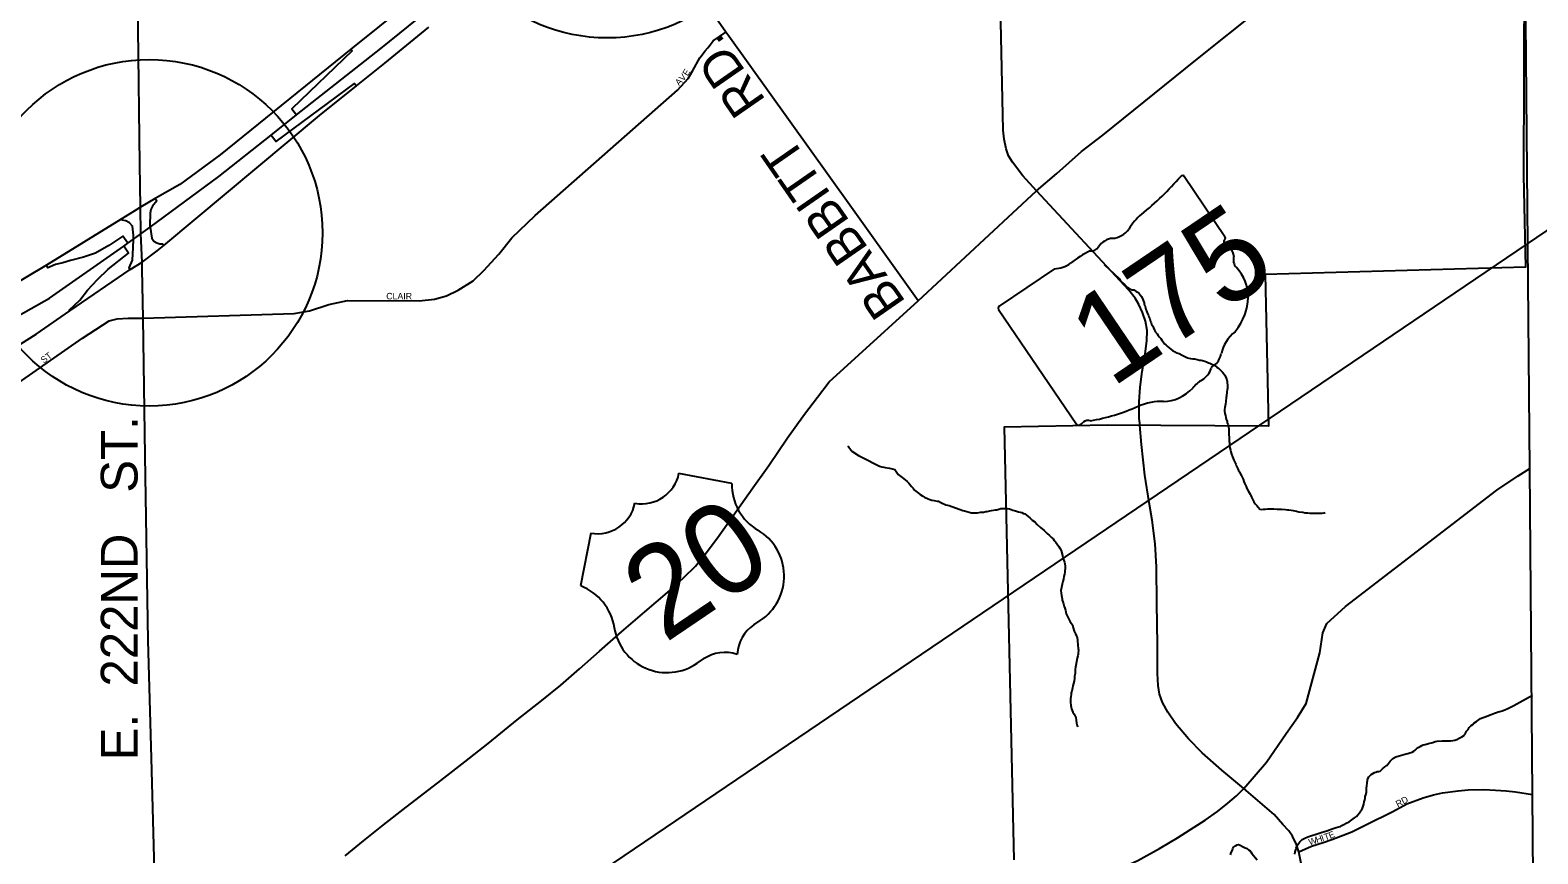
# Model space of a CAD drawing. Extents: x 2139079 to 2262683, y 1235796 to 1334992.
# Drawn here: x 2234072 to 2245568, y 1303635 to 1309915 of the extents above; entities that cross this region are included whole.
import ezdxf

# ---------------------------------------------------------------- set-up
doc = ezdxf.new("R2010")
doc.units = 0
for name, color, linetype in [('GM_X_Adjacent_County', 7, 'Continuous'), ('GM_X_City_Street', 7, 'Continuous'), ('GM_X_City_Street_Text', 7, 'Continuous'), ('GM_X_Interchange_Ramps', 7, 'Continuous'), ('GM_X_Interstate_Route', 7, 'Continuous'), ('GM_X_Minor_River', 7, 'Continuous'), ('GM_X_State_Location', 7, 'Continuous'), ('GM_X_State_Route', 7, 'Continuous'), ('GM_X_State_Shield', 7, 'Continuous'), ('GM_X_US_Location', 7, 'Continuous'), ('GM_X_US_Route', 7, 'Continuous'), ('GM_X_US_Shield', 7, 'Continuous'), ('SH_Text', 7, 'Continuous')]:
    doc.layers.add(name, color=color, linetype=linetype)

msp = doc.modelspace()

# ---------------------------------------------------------------- linework, layer by layer
at = {"layer": 'GM_X_Adjacent_County'}
msp.add_lwpolyline([(2245541, 1302192), (2245528, 1304087), (2245507, 1306573), (2245466, 1311124), (2245451, 1311744), (2245406, 1312275), (2245366, 1313013), (2245298, 1316197), (2245294, 1316360), (2245278, 1317130), (2245271, 1317437), (2245264, 1317789), (2245234, 1319644), (2245190, 1321250), (2245174, 1321990), (2245155, 1322872), (2245144, 1323376), (2245140, 1323785), (2245134, 1324581), (2245318, 1324775), (2245503, 1324980), (2245556, 1325020), (2245646, 1325055)], dxfattribs=at)
at = {"layer": 'GM_X_City_Street'}
for points in [[(2234909, 1308893), (2234870, 1311991), (2234797, 1316346), (2234781, 1316477)], [(2241391, 1313747), (2241308, 1313700), (2241239, 1313644), (2240849, 1313342), (2240048, 1312674), (2239503, 1312219), (2238476, 1311361), (2238395, 1311294), (2238315, 1311229), (2237753, 1310771), (2237032, 1310186), (2236735, 1309945), (2236518, 1309769), (2235520, 1308963), (2235213, 1308739), (2235026, 1308631), (2234914, 1308565), (2234865, 1308535)], [(2239398, 1309868), (2239376, 1309899), (2238560, 1311072), (2238478, 1311183), (2238395, 1311294)], [(2234926, 1308146), (2235041, 1308233), (2235092, 1308272), (2236278, 1309265), (2236560, 1309490), (2236776, 1309663), (2237111, 1309938)], [(2239257, 1309803), (2239281, 1309833), (2239376, 1309899)], [(2240321, 1308580), (2239398, 1309868)], [(2234934, 1307718), (2236085, 1307754), (2236202, 1307776), (2236350, 1307823), (2236491, 1307854), (2237039, 1307852), (2237154, 1307863), (2237247, 1307889), (2237336, 1307932), (2237449, 1308004), (2237530, 1308082), (2237645, 1308208), (2237745, 1308332), (2237923, 1308502), (2239008, 1309457), (2239090, 1309546), (2239124, 1309607), (2239179, 1309703), (2239220, 1309758), (2239239, 1309781), (2239257, 1309803)], [(2234927, 1308092), (2234926, 1308146), (2234917, 1308361), (2234914, 1308565), (2234909, 1308893)], [(2240844, 1307851), (2240321, 1308580)], [(2234865, 1308535), (2234767, 1308474), (2234196, 1308122), (2232556, 1307145), (2232165, 1306913), (2231754, 1306642), (2231295, 1306315)], [(2231412, 1306001), (2232025, 1306429), (2232297, 1306605), (2232573, 1306755), (2232743, 1306842), (2233049, 1306993), (2233510, 1307216), (2234119, 1307596), (2234374, 1307775), (2234835, 1308090), (2234926, 1308146)], [(2234934, 1307718), (2234927, 1308092)], [(2231078, 1305046), (2231495, 1305379), (2231714, 1305558), (2232083, 1305854), (2232970, 1306469), (2233503, 1306893), (2233761, 1307074), (2234472, 1307567), (2234675, 1307698), (2234735, 1307713), (2234819, 1307719), (2234934, 1307718)], [(2234950, 1306670), (2234934, 1307718)], [(2234997, 1304365), (2234973, 1305262), (2234950, 1306670)], [(2235037, 1302845), (2234997, 1304365)], [(2243746, 1303651), (2243841, 1303694), (2243931, 1303722), (2243998, 1303744), (2244149, 1303802), (2244261, 1303858), (2244463, 1303958), (2244569, 1304016), (2244693, 1304062), (2244773, 1304086), (2244841, 1304100), (2244961, 1304116), (2245037, 1304124), (2245157, 1304125), (2245245, 1304121), (2245325, 1304115), (2245398, 1304107), (2245528, 1304087)]]:
    msp.add_lwpolyline(points, dxfattribs=at)
at = {"layer": 'GM_X_Interchange_Ramps'}
for points in [[(2236518, 1309769), (2236528, 1309757), (2236067, 1309315), (2236104, 1309268)], [(2235909, 1309114), (2235947, 1309067), (2236545, 1309508), (2236560, 1309490)], [(2235026, 1308631), (2235037, 1308613), (2235004, 1308573), (2234993, 1308547), (2234987, 1308519), (2234985, 1308426), (2234987, 1308413), (2235000, 1308329), (2235016, 1308307), (2235039, 1308294), (2235061, 1308286), (2235082, 1308285), (2235092, 1308272)], [(2234835, 1308090), (2234827, 1308103), (2234853, 1308162), (2234858, 1308257), (2234860, 1308321), (2234860, 1308352), (2234852, 1308420), (2234829, 1308447), (2234801, 1308461), (2234774, 1308465), (2234767, 1308474)], [(2234817, 1308291), (2234779, 1308345), (2234672, 1308272), (2234571, 1308215), (2234480, 1308184), (2234379, 1308159), (2234320, 1308142), (2234264, 1308127), (2234208, 1308103), (2234196, 1308122)], [(2234374, 1307775), (2234370, 1307780), (2234450, 1307856), (2234508, 1307932), (2234585, 1308015), (2234667, 1308092), (2234823, 1308215), (2234786, 1308269)]]:
    msp.add_lwpolyline(points, dxfattribs=at)
at = {"layer": 'GM_X_Interstate_Route'}
for points in [[(2245142, 1323484), (2245178, 1321773), (2245406, 1312275), (2245451, 1311744), (2245466, 1311124), (2245458, 1308807), (2245473, 1308109), (2243489, 1308053), (2243515, 1306895), (2242283, 1306903), (2241498, 1306888), (2241571, 1303589)], [(2245142, 1323484), (2245178, 1321773), (2245406, 1312275), (2245451, 1311744), (2245466, 1311124), (2245458, 1308807), (2245473, 1308109), (2243489, 1308053), (2243515, 1306895), (2242283, 1306903), (2241498, 1306888), (2241571, 1303589)], [(2232924, 1307142), (2234220, 1307872), (2234786, 1308269), (2234817, 1308291), (2234860, 1308321), (2234917, 1308361), (2234987, 1308413), (2235511, 1308800), (2235909, 1309114), (2236104, 1309268), (2236747, 1309775), (2237510, 1310396), (2237574, 1310448), (2238417, 1311133), (2238478, 1311183), (2238522, 1311219), (2239158, 1311738), (2239253, 1311815), (2240623, 1312932), (2240702, 1312997), (2241356, 1313531), (2241390, 1313558)]]:
    msp.add_lwpolyline(points, dxfattribs=at)
at = {"layer": 'GM_X_Minor_River'}
for points in [[(2242261, 1308127), (2242378, 1308019), (2242389, 1307999), (2242403, 1307987), (2242413, 1307980), (2242425, 1307966), (2242439, 1307954), (2242451, 1307946), (2242461, 1307940), (2242475, 1307936), (2242488, 1307934), (2242504, 1307922), (2242516, 1307917), (2242528, 1307907), (2242536, 1307897), (2242546, 1307883), (2242556, 1307861), (2242561, 1307849), (2242565, 1307837), (2242567, 1307827), (2242571, 1307817), (2242573, 1307807), (2242575, 1307797), (2242579, 1307785), (2242583, 1307775), (2242588, 1307759), (2242594, 1307749), (2242598, 1307739), (2242602, 1307729), (2242608, 1307713), (2242612, 1307703), (2242614, 1307693), (2242619, 1307683), (2242623, 1307673), (2242631, 1307657), (2242637, 1307645), (2242645, 1307627), (2242653, 1307613), (2242664, 1307599), (2242672, 1307587), (2242680, 1307577), (2242692, 1307563), (2242700, 1307552), (2242710, 1307538), (2242721, 1307524), (2242731, 1307516), (2242741, 1307506), (2242759, 1307490), (2242769, 1307482), (2242785, 1307470), (2242797, 1307466), (2242815, 1307456), (2242832, 1307449), (2242856, 1307437), (2242872, 1307429), (2242882, 1307423), (2242896, 1307417), (2242906, 1307415), (2242918, 1307411), (2242936, 1307408), (2242950, 1307408), (2242970, 1307404), (2242988, 1307400), (2242998, 1307398), (2243012, 1307396), (2243029, 1307391), (2243041, 1307387), (2243057, 1307379), (2243067, 1307377), (2243087, 1307367), (2243103, 1307361), (2243123, 1307342), (2243133, 1307338), (2243150, 1307320), (2243162, 1307308), (2243174, 1307294), (2243180, 1307284), (2243192, 1307262), (2243196, 1307248), (2243199, 1307236), (2243199, 1307224), (2243201, 1307214), (2243201, 1307184), (2243199, 1307174), (2243196, 1307156), (2243194, 1307126), (2243192, 1307114), (2243188, 1307083), (2243185, 1307063), (2243181, 1307039), (2243179, 1307023), (2243179, 1307009), (2243181, 1306993), (2243185, 1306977), (2243188, 1306961), (2243192, 1306949)], [(2243192, 1306949), (2243198, 1306931), (2243200, 1306921), (2243206, 1306907), (2243210, 1306895), (2243211, 1306867), (2243211, 1306843), (2243211, 1306829), (2243213, 1306811), (2243214, 1306781), (2243216, 1306769), (2243216, 1306751), (2243220, 1306731), (2243225, 1306713), (2243227, 1306699), (2243233, 1306681), (2243239, 1306663), (2243245, 1306649), (2243249, 1306637), (2243254, 1306627), (2243260, 1306615), (2243264, 1306605), (2243268, 1306595), (2243274, 1306581), (2243280, 1306571), (2243286, 1306559), (2243292, 1306547), (2243299, 1306535), (2243309, 1306517), (2243321, 1306491), (2243327, 1306475), (2243332, 1306461), (2243338, 1306447), (2243344, 1306435), (2243350, 1306421), (2243360, 1306403), (2243366, 1306389), (2243373, 1306377), (2243379, 1306366), (2243385, 1306354), (2243391, 1306340), (2243397, 1306330), (2243403, 1306320), (2243413, 1306304), (2243424, 1306290), (2243434, 1306278), (2243448, 1306262), (2243460, 1306260), (2243476, 1306262), (2243492, 1306262), (2243510, 1306265), (2243530, 1306265), (2243544, 1306265), (2243554, 1306265), (2243580, 1306263), (2243592, 1306264), (2243612, 1306262), (2243644, 1306260), (2243658, 1306258), (2243670, 1306258), (2243686, 1306255), (2243701, 1306253), (2243715, 1306249), (2243727, 1306247), (2243745, 1306243), (2243775, 1306239), (2243793, 1306236), (2243805, 1306236), (2243815, 1306234), (2243829, 1306232), (2243839, 1306232), (2243851, 1306232), (2243863, 1306232), (2243875, 1306232), (2243887, 1306233), (2243899, 1306233), (2243911, 1306233), (2243923, 1306233), (2243939, 1306235), (2243945, 1306237)], [(2240305, 1306744), (2240313, 1306736), (2240338, 1306704), (2240389, 1306671), (2240444, 1306644), (2240517, 1306607), (2240533, 1306599), (2240549, 1306592), (2240566, 1306586), (2240580, 1306584), (2240590, 1306580), (2240624, 1306575), (2240654, 1306568), (2240666, 1306566), (2240691, 1306528), (2240732, 1306497), (2240759, 1306475), (2240771, 1306461), (2240781, 1306449), (2240792, 1306436), (2240804, 1306422), (2240814, 1306408), (2240824, 1306400), (2240835, 1306392), (2240845, 1306384), (2240857, 1306375), (2240879, 1306363), (2240894, 1306353), (2240908, 1306347), (2240920, 1306342), (2240932, 1306336), (2240948, 1306332), (2240966, 1306329), (2240987, 1306325), (2240997, 1306325), (2241021, 1306312), (2241053, 1306296), (2241080, 1306291), (2241183, 1306252), (2241197, 1306249), (2241213, 1306245), (2241231, 1306239), (2241249, 1306236), (2241272, 1306234), (2241294, 1306234), (2241318, 1306239), (2241342, 1306241), (2241358, 1306244), (2241370, 1306246), (2241388, 1306250), (2241402, 1306253), (2241418, 1306255), (2241432, 1306259), (2241442, 1306259), (2241472, 1306268), (2241502, 1306269), (2241524, 1306267), (2241538, 1306265), (2241564, 1306256), (2241584, 1306250), (2241609, 1306243), (2241633, 1306237), (2241645, 1306231), (2241655, 1306227), (2241680, 1306210), (2241696, 1306194), (2241712, 1306178), (2241733, 1306167), (2241751, 1306147), (2241776, 1306123), (2241804, 1306100), (2241827, 1306078), (2241843, 1306062), (2241860, 1306048), (2241872, 1306037), (2241880, 1306025), (2241891, 1306013), (2241903, 1305997), (2241915, 1305979), (2241924, 1305965), (2241932, 1305949), (2241945, 1305899), (2241952, 1305878), (2241958, 1305860), (2241960, 1305846), (2241963, 1305828), (2241963, 1305815), (2241963, 1305805), (2241961, 1305795), (2241960, 1305783), (2241958, 1305767), (2241954, 1305749), (2241951, 1305729), (2241947, 1305711), (2241941, 1305690), (2241936, 1305666), (2241930, 1305644), (2241933, 1305622), (2241935, 1305606), (2241937, 1305592), (2241940, 1305580)], [(2241940, 1305580), (2241942, 1305570), (2241946, 1305556), (2241950, 1305542), (2241953, 1305530), (2241957, 1305520), (2241961, 1305508), (2241965, 1305492), (2241970, 1305464), (2241983, 1305440), (2241993, 1305420), (2242001, 1305404), (2242012, 1305392), (2242020, 1305381), (2242024, 1305359), (2242033, 1305333), (2242043, 1305313), (2242050, 1305295), (2242054, 1305285), (2242057, 1305261), (2242059, 1305227), (2242064, 1305201), (2242066, 1305189), (2242064, 1305168), (2242063, 1305158), (2242061, 1305144), (2242055, 1305128), (2242044, 1305072), (2242043, 1305058), (2242041, 1305043), (2242041, 1305029), (2242040, 1305009), (2242036, 1304991), (2242034, 1304975), (2242031, 1304953), (2242027, 1304933), (2242023, 1304917), (2242020, 1304900), (2242018, 1304888), (2242014, 1304876), (2242010, 1304862), (2242009, 1304850), (2242007, 1304834), (2242005, 1304816), (2242004, 1304792), (2242008, 1304766), (2242013, 1304740), (2242021, 1304716), (2242032, 1304700), (2242038, 1304690), (2242044, 1304674), (2242047, 1304654), (2242051, 1304632), (2242056, 1304612), (2242060, 1304608), (2242060, 1304606)], [(2244366, 1304266), (2244382, 1304284), (2244400, 1304299), (2244416, 1304309), (2244427, 1304321), (2244433, 1304331), (2244441, 1304343), (2244461, 1304363), (2244485, 1304374), (2244509, 1304382), (2244529, 1304388), (2244547, 1304392), (2244563, 1304397), (2244577, 1304401), (2244591, 1304405), (2244609, 1304411), (2244621, 1304417), (2244631, 1304425), (2244643, 1304436), (2244656, 1304446), (2244670, 1304454), (2244684, 1304462), (2244694, 1304466), (2244708, 1304470), (2244734, 1304477), (2244766, 1304485), (2244786, 1304491), (2244800, 1304495), (2244838, 1304498), (2244870, 1304496), (2244902, 1304497), (2244920, 1304499), (2244934, 1304501), (2244950, 1304507), (2244968, 1304517), (2244988, 1304528), (2245002, 1304536), (2245016, 1304556), (2245024, 1304570), (2245036, 1304584), (2245045, 1304598), (2245059, 1304613), (2245071, 1304621), (2245079, 1304631), (2245101, 1304645), (2245131, 1304668), (2245179, 1304684), (2245211, 1304698), (2245237, 1304707), (2245253, 1304713), (2245264, 1304717), (2245278, 1304721), (2245296, 1304726), (2245316, 1304734), (2245338, 1304744), (2245364, 1304756), (2245384, 1304767), (2245527, 1304844)], [(2243714, 1303633), (2243718, 1303651), (2243722, 1303667), (2243725, 1303679), (2243733, 1303699), (2243745, 1303716), (2243753, 1303728), (2243771, 1303744), (2243791, 1303754), (2243815, 1303765), (2243837, 1303773), (2243853, 1303777), (2243871, 1303783), (2243922, 1303800), (2243942, 1303806), (2243960, 1303812), (2243978, 1303819), (2243992, 1303823), (2244008, 1303829), (2244030, 1303837), (2244050, 1303841), (2244062, 1303845), (2244072, 1303852), (2244088, 1303858), (2244106, 1303870), (2244130, 1303880), (2244150, 1303895), (2244170, 1303909), (2244184, 1303921), (2244195, 1303933), (2244207, 1303947), (2244217, 1303962), (2244225, 1303972), (2244231, 1303984), (2244237, 1303998), (2244241, 1304014), (2244244, 1304032), (2244248, 1304048), (2244250, 1304060), (2244252, 1304072), (2244256, 1304086), (2244260, 1304104), (2244261, 1304118), (2244261, 1304133), (2244265, 1304157), (2244267, 1304171), (2244267, 1304183), (2244272, 1304209), (2244280, 1304223), (2244296, 1304241), (2244310, 1304249), (2244322, 1304256), (2244332, 1304258), (2244342, 1304262), (2244356, 1304264), (2244366, 1304266)], [(2243225, 1303628), (2243229, 1303646), (2243239, 1303664), (2243243, 1303676), (2243248, 1303686), (2243262, 1303696), (2243274, 1303703), (2243286, 1303707), (2243298, 1303701), (2243317, 1303691), (2243337, 1303681), (2243351, 1303675), (2243361, 1303665), (2243373, 1303659), (2243379, 1303650), (2243387, 1303638), (2243428, 1303590)]]:
    msp.add_lwpolyline(points, dxfattribs=at)
at = {"layer": 'GM_X_State_Route'}
for points in [[(2241744, 1308690), (2241641, 1308805), (2241562, 1308908), (2241532, 1308957), (2241513, 1309011), (2241499, 1309083), (2241491, 1309152), (2241462, 1310453)], [(2242532, 1306918), (2242529, 1306955), (2242527, 1307082), (2242535, 1307192), (2242551, 1307312), (2242573, 1307447), (2242586, 1307546), (2242588, 1307625), (2242577, 1307696), (2242553, 1307761), (2242525, 1307824), (2242498, 1307872), (2242448, 1307933), (2241744, 1308690)], [(2243326, 1304133), (2243157, 1304273), (2243007, 1304405), (2242903, 1304511), (2242806, 1304628), (2242746, 1304715), (2242707, 1304788), (2242684, 1304852), (2242673, 1304918), (2242667, 1305010), (2242667, 1305232), (2242662, 1305543), (2242660, 1305823), (2242649, 1305998), (2242628, 1306180), (2242603, 1306313), (2242570, 1306521), (2242546, 1306755), (2242533, 1306903), (2242532, 1306918)], [(2243759, 1303247), (2243764, 1303275), (2243770, 1303379), (2243769, 1303477), (2243763, 1303561), (2243746, 1303651), (2243727, 1303707), (2243698, 1303769), (2243669, 1303810), (2243624, 1303860), (2243557, 1303935), (2243326, 1304133)]]:
    msp.add_lwpolyline(points, dxfattribs=at)
at = {"layer": 'GM_X_State_Shield'}
for p, q in [((2243182, 1308340), (2242872, 1308798)), ((2243182, 1308340), (2243182, 1308340)), ((2241882, 1308096), (2241460, 1307810)), ((2241456, 1307785), (2242049, 1306911))]:
    msp.add_line(p, q, dxfattribs=at)
for centre, major_axis, start_param, end_param in [((2241566, 1309621), (1528, 1035), 4.814394, 5.042369), ((2242855, 1308789), (16, 10.9), 6.141152, 7.989035), ((2242750, 1308294), (307, 208), 1.699011, 2.107814), ((2242311, 1308226), (97.1, 65.8), 0.950623, 2.079405), ((2242343, 1308450), (117, 79), 4.081561, 5.145723), ((2243166, 1308327), (17.2, 11.6), 5.05454, 6.418171), ((2242369, 1307709), (581, 394), 1.404758, 1.657858), ((2242174, 1308281), (46.7, 31.6), 3.836095, 5.185415), ((2243201, 1308304), (24.8, 16.8), 1.883978, 3.671073), ((2243083, 1308140), (149, 101), 5.934695, 6.695948), ((2241914, 1308266), (162, 110), 4.042523, 4.731795), ((2243369, 1308188), (108, 73), 2.387724, 3.262537), ((2242924, 1307801), (382, 259), 5.101752, 6.440018), ((2241472, 1307798), (16.7, 11.3), 1.712693, 3.28349), ((2243390, 1307460), (209, 142), 1.647645, 2.488434), ((2243015, 1307442), (123, 84), 4.937069, 5.64225), ((2242948, 1307344), (117, 79), 4.691044, 5.507374), ((2243111, 1307331), (32.9, 22.3), 1.147584, 2.315152), ((2242761, 1307313), (219, 148), 4.026481, 4.996735), ((2243092, 1307096), (180, 122), 1.495662, 1.94098), ((2242617, 1306722), (345, 234), 0.823519, 1.323587), ((2242129, 1306891), (46.3, 31.4), 0.519207, 1.627899), ((2242181, 1308073), (1103, 747), 4.195997, 4.488961), ((2242067, 1306920), (16.8, 11.4), 3.00124, 4.508301), ((2242009, 1307011), (129, 87), 4.665946, 4.897461)]:
    msp.add_ellipse(centre, major_axis=major_axis, ratio=0.8, start_param=start_param, end_param=end_param, dxfattribs=at)
at = {"layer": 'GM_X_US_Route'}
msp.add_lwpolyline([(2202868, 1295541), (2210354, 1284489), (2249318, 1310882), (2241832, 1321934)], close=True, dxfattribs=at)
for points in [[(2241744, 1308690), (2241900, 1308822), (2242089, 1308990), (2242250, 1309114), (2242960, 1309687), (2243940, 1310472), (2244832, 1311181), (2245228, 1311548), (2245343, 1311654), (2245451, 1311744)], [(2236475, 1303620), (2236614, 1303735), (2236766, 1303857), (2236939, 1303990), (2237180, 1304177), (2237387, 1304337), (2237564, 1304476), (2237785, 1304657), (2237974, 1304804), (2238118, 1304922), (2238261, 1305045), (2238414, 1305181), (2238581, 1305328), (2238759, 1305480), (2238950, 1305644), (2239057, 1305743), (2239145, 1305828), (2239220, 1305921), (2239313, 1306044), (2239430, 1306209), (2239583, 1306425), (2239705, 1306596), (2239846, 1306806), (2239977, 1306987), (2240074, 1307116), (2240165, 1307233), (2240844, 1307851), (2241744, 1308690)], [(2243326, 1304133), (2243499, 1304333), (2243648, 1304553), (2243735, 1304675), (2243800, 1304782), (2243905, 1305169), (2243927, 1305319), (2243958, 1305392), (2244100, 1305522), (2245255, 1306407), (2245418, 1306516), (2245507, 1306573)], [(2242407, 1303533), (2242517, 1303585), (2242683, 1303676), (2242820, 1303758), (2242919, 1303820), (2243030, 1303892), (2243125, 1303958), (2243204, 1304021), (2243269, 1304078), (2243326, 1304133)]]:
    msp.add_lwpolyline(points, dxfattribs=at)
at = {"layer": 'GM_X_US_Shield'}
for p, q in [((2239422, 1306458), (2239019, 1306536)), ((2238347, 1306080), (2238269, 1305678)), ((2239591, 1305382), (2239639, 1305414)), ((2239159, 1305089), (2239207, 1305121))]:
    msp.add_line(p, q, dxfattribs=at)
for centre, radius, start, end in [((2238735, 1306594), 290, 259.6844, 348.5384), ((2239828, 1306452), 406, 179.1105, 239.5643), ((2238399, 1306366), 290, 259.6844, 348.5384), ((2239415, 1305753), 406, 303.4731, 59.2795), ((2238125, 1305298), 406, 8.6585, 69.1123), ((2238927, 1305423), 406, 188.9433, 304.7497), ((2239753, 1305142), 290, 124.1114, 177.2415), ((2239369, 1304881), 290, 70.9813, 124.1114)]:
    msp.add_arc(centre, radius, start, end, dxfattribs=at)
at = {"layer": 'SH_Text'}
for centre in [(2238471, 1311176), (2234980, 1308370)]:
    msp.add_circle(centre, 1321, dxfattribs=at)

# ---------------------------------------------------------------- texts
at = {"layer": 'GM_X_City_Street_Text'}
for s, rotation, p in [('V', 49.2133, (2239051, 1309521)), ('E', 58.4149, (2239085, 1309561)), ('A', 47.1955, (2239020, 1309487)), ('CLAIR', 0, (2236787, 1307862)), ('ST', 37.5735, (2234176, 1307372)), ('RD', 27.882, (2244500, 1303989)), ('W', 17.8395, (2243829, 1303699)), ('H', 17.8356, (2243883, 1303717)), ('I', 17.8543, (2243925, 1303730)), ('T', 17.856, (2243946, 1303737)), ('E', 22.5901, (2243984, 1303749))]:
    msp.add_text(s, height=50, rotation=rotation, dxfattribs=at).set_placement(p)
at = {"layer": 'GM_X_Interchange_Ramps'}
for s, rotation, p in [('BABBITT   RD. ', 124.7563, (2240754, 1307839)), ('E.  222ND   ST.', 90, (2234891, 1304349))]:
    msp.add_text(s, height=280, rotation=rotation, dxfattribs=at).set_placement(p)
at = {"layer": 'GM_X_State_Location'}
for s in ['s', 'r']:
    msp.add_text(s, height=1, dxfattribs=at).set_placement((2242587, 1307434))
msp.add_text('175', height=1, rotation=0, dxfattribs=at).set_placement((2242234, 1307361))
at = {"layer": 'GM_X_State_Shield'}
msp.add_text('175', height=696.1, rotation=34.1114, dxfattribs=at).set_placement((2242316, 1307182))
at = {"layer": 'GM_X_US_Location'}
for s in ['0', '/']:
    msp.add_text(s, height=1, dxfattribs=at).set_placement((2239387, 1306138))
msp.add_text('20', height=1, rotation=0, dxfattribs=at).set_placement((2239181, 1305931))
at = {"layer": 'GM_X_US_Shield'}
msp.add_text('20', height=696.1, rotation=34.1114, dxfattribs=at).set_placement((2238911, 1305237))

doc.saveas('drawing.dxf')
